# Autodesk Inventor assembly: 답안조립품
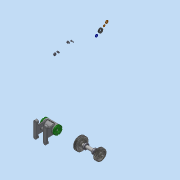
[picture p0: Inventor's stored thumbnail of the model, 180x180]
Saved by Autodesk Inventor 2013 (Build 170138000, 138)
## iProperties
Created: 2015-11
Part Number: 답안조립품
Document SubType Name: Assembly
Designer: Administrator
Author: Administrator
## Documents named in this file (16)
- C:\Users\Administrator\Desktop\451110V1049\답안조립품.iam
- C:\Users\Administrator\Desktop\451110V1049\본체.ipt
- C:\Users\Administrator\Desktop\451110V1049\V벨트풀리.ipt
- C:\Users\Administrator\Desktop\451110V1049\너트 M 8.ipt
- C:\Users\Administrator\Desktop\451110V1049\니플 M 6 x 0.75.ipt
- C:\Users\Administrator\Desktop\451110V1049\베어링 15 x 32 x 9.ipt
- C:\Users\Administrator\Desktop\451110V1049\볼트 M 6 x 8.ipt
- C:\Users\Administrator\Desktop\451110V1049\볼트 M4 x 12.ipt
- C:\Users\Administrator\Desktop\451110V1049\스퍼기어.ipt
- C:\Users\Administrator\Desktop\451110V1049\스프링와셔 8.ipt
- C:\Users\Administrator\Desktop\451110V1049\오일 실 15 25 7.ipt
- C:\Users\Administrator\Desktop\451110V1049\와셔 6x11.5.ipt
- C:\Users\Administrator\Desktop\451110V1049\와셔 8x17.ipt
- C:\Users\Administrator\Desktop\451110V1049\축.ipt
- C:\Users\Administrator\Desktop\451110V1049\커버.ipt
- C:\Users\Administrator\Desktop\451110V1049\키 3 x 3 x 12.ipt
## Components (4 placed, 3 different names)
1. V벨트풀리:1
2. KS B 2023 6002 - 15 x 32 x 9:1
3. ISO 4762 M4 x 12:1
4. KS B 2023 6002 - 15 x 32 x 9:2
